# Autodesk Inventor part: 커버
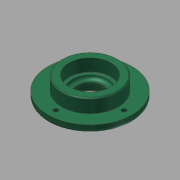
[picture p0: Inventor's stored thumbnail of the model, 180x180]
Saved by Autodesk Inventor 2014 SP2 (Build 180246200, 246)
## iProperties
Company: 한국ATC센터
Created: 2014-10
Part Number: 커버
Document SubType Name: Modeling
Designer: KYOUNG IL JANG
Density: 7.86 g/cm^3
Mass: 351.567 g
Surface Area: 161.165 cm^2
Volume: 44.7286 cm^3
Material: 강철, 연강
Appearance: 강철
Author: KYOUNG IL JANG
Revision Number: 1
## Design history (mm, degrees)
sketch "스케치1"
  geometry: C1 r 40 at (0, 0); 1 further point
  constraints: 1 centre point, 1 coincident
  dimensions: "d0" = 80 diameter of C1
extrude "돌출1" new body sketch "스케치1" distance "d1" = 7; taper "d2" = 0 deg
sketch "스케치2"
  geometry: C1 r 27 at (0, 0); 1 further point
  constraints: 1 centre point, 1 coincident
  dimensions: "d3" = 54 diameter of C1
extrude "돌출2" join sketch "스케치2" distance "d4" = 13; taper "d5" = 0 deg
sketch "스케치3"
  geometry: C1 r 20 at (0, 0); 1 further point
  constraints: 1 centre point, 1 coincident
  dimensions: "d6" = 40 diameter of C1
extrude "돌출3" join sketch "스케치3" distance "d7" = 5; taper "d8" = 0 deg
hole "구멍1" diameter "d11" = 25; stored, may be unused: countersink angle "d15" = 90 deg, drill point angle "d17" = 118 deg; dims "d9" = 10, "d10" = 10, "d12" = 6, "d13" = 32, "d14" = 8.3, "d16" = 8
hole "구멍2" diameter "d20" = 34; stored, may be unused: countersink angle "d24" = 90 deg, drill point angle "d26" = 0 deg; dims "d18" = 10, "d19" = 10, "d21" = 6, "d22" = 40, "d23" = 12, "d25" = 3
fillet "모깎기2" dims "d34" = 3
fillet "모깎기1" dims "d27" = 0.3
chamfer "모따기1" distance "d28" = 1; stored, may be unused: second distance "d29" = 2, angle "d30" = 45 deg
chamfer "모따기2" distance "d31" = 1.2; stored, may be unused: second distance "d32" = 2, angle "d33" = 30 deg
sketch "스케치4" dims "d35" = 65
  geometry: 3 further points
  constraints: 2 horizontal alignment, 1 coincident, 2 other
hole "구멍3" sketch "스케치4" at (32.5, 0) diameter "d36" = 4.5; stored, may be unused: countersink angle "d40" = 90 deg, drill point angle "d42" = 118 deg; dims "d37" = 6, "d38" = 8, "d39" = 4.4, "d41" = 13
node "솔리드1"
pattern_circular "원형 패턴1" dims angle "d44" = 360 deg
